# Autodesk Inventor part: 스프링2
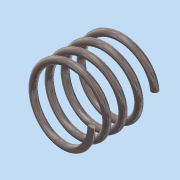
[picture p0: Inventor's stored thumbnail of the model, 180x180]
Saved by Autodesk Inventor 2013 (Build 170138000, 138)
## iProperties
Created: 2016-07
Part Number: 스프링2
Material: 스테인리스강
Document SubType Name: Modeling
Designer: Administrator
Density: 8.08 g/cm^3
Mass: 6.29661 g
Surface Area: 15.7973 cm^2
Volume: 0.779284 cm^3
Author: Administrator
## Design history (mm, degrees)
sketch "스케치1"
  geometry: L1 (0, 0)-(0, 19.5); L2 (0, 19.5)-(11.971, 19.5); C1 r 1 at (10, 0)
  constraints: 4 end point, 1 centre point, 1 horizontal alignment, 1 perpendicular, 1 vertical
  dimensions: "d0" = 19.5 distance of L1.start L1.end (derived); "d1" = 2 diameter of C1; "d2" = 20 diameter of C1.centre L1
feature "코일1" sketch "스케치1" pitch "d3" = 10; turns "d5" = 4; dims "d4" = 19.5 (= d0), "d6" = 0, angle "d7" = 90 deg, angle "d8" = 90 deg, "d9" = 0, "d10" = 0
sketch "스케치2"
  geometry: L1 (25, 15)-(0, 15); L2 (0, 15)-(0, -15); L3 (0, -15)-(25, -15); L4 (25, -15)-(25, 15); 2 further points
  constraints: 8 end point, 2 parallel, 1 coincident, 1 horizontal, 1 midpoint, 1 perpendicular
  dimensions: "d11" = 30 distance between parallel lines of L3 L1; "d13" = 25 distance of L1.start L1.end (derived)
extrude "돌출1" sketch "스케치2" stored distance "d14" = 30; taper "d15" = 0 deg
node "솔리드1"
